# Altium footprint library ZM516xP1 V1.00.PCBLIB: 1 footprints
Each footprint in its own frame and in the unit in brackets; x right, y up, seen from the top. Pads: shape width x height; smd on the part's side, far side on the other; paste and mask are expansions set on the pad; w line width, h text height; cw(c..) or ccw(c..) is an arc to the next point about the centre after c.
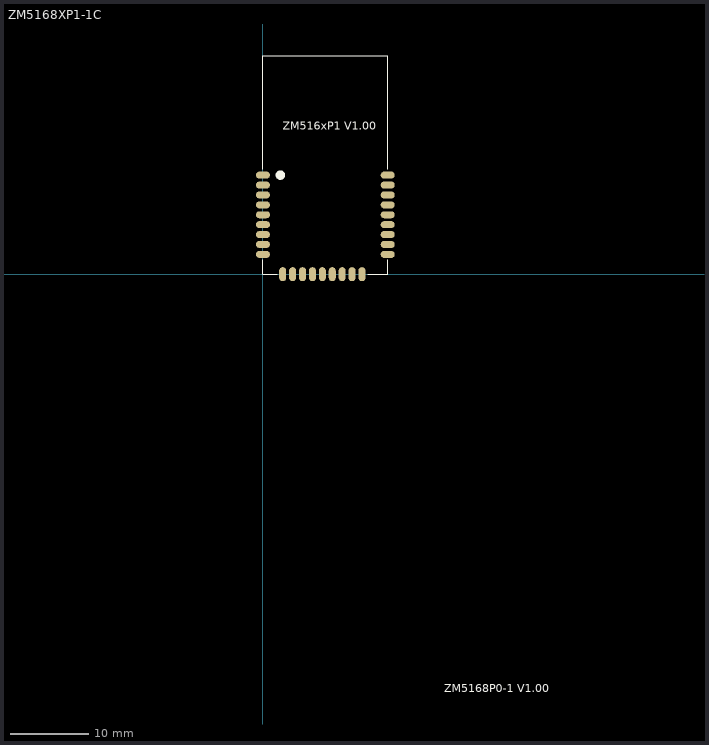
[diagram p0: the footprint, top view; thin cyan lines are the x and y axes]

## ZM5168XP1-1C [mm]
pads (27):
  oval 1.8x0.9 smd: 1(0,12.7) 2(0,11.43) 3(0,10.16) 4(0,8.89) 5(0,7.62) 6(0,6.35) 7(0,5.08) 8(0,3.81) 9(0,2.54) 19(16,2.54) 20(16,3.81) 21(16,5.08) 22(16,6.35) 23(16,7.62) 24(16,8.89) 25(16,10.16) 26(16,11.43) 27(16,12.7)
  oval 0.9x1.8 smd: 10(2.54,0) 11(3.81,0) 12(5.08,0) 13(6.35,0) 14(7.62,0) 15(8.89,0) 16(10.16,0) 17(11.43,0) 18(12.7,0)
Top Overlay:
  circle w0.61: c2.235,12.7 r0.305
  lines w0.127: 0,1.829 0,0 1.829,0 ; 0,13.437 0,28 16,28 16,13.437 ; 13.462,0 16,0 16,1.829
  text "ZM516xP1 V1.00" at 2.54,18.542 h1.02
  text "ZM5168P0-1 V1.00" at 23.241,-53.594 h1.02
